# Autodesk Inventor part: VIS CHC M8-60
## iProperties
Created: 2004-11
Part Number: VIS CHC M8-60
Document SubType Name: Modeling
Designer: Bruno
Manufacturer: Standard
Standards Organization: Custom
Author: Bruno
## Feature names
1. Base1
